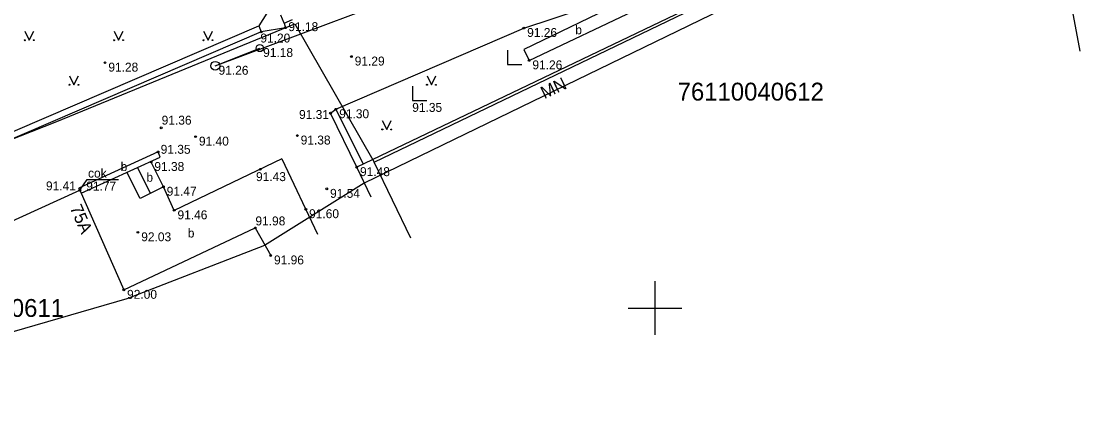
# Model space of a CAD drawing. Extents: x 634272 to 634544, y 247463 to 247653.
# Drawn here: x 634414.5 to 634473.8, y 247493.7 to 247516.1 of the extents above; entities that cross this region are included whole.
import ezdxf

# ---------------------------------------------------------------- set-up
doc = ezdxf.new("R2010")
doc.units = 0
for name, color, linetype in [('BUVE_BDET_####_####_#', 7, 'Continuous'), ('BUVE_BDET_####_TKST_#', 7, 'Continuous'), ('BUVE_COKL_####_####_#', 7, 'Continuous'), ('BUVE_EKAS_####_####_#', 7, 'Continuous'), ('BUVE_EKAS_ADRS_TKST_#', 7, 'Continuous'), ('BUVE_EKAS_RAKS_TKST_#', 7, 'Continuous'), ('CELI_CMAL_####_####_#', 7, 'Continuous'), ('CELI_SEGL_####_####_#', 7, 'Continuous'), ('ELEK_ELEM_####_####_#', 7, 'Continuous'), ('ELEK_STUT_####_####_#', 7, 'Continuous'), ('ELEK_VADV_ZSPR_####_#', 7, 'Continuous'), ('GEOD_ELEM_####_####_#', 7, 'Continuous'), ('NORB_ELEM_####_####_#', 7, 'Continuous'), ('NORB_ZOGS_KONT_####_#', 7, 'Continuous'), ('RAMI_UZMR_####_####_#', 7, 'Continuous'), ('RELJ_AATZ_####_TKST_#', 7, 'Continuous'), ('RELJ_ELEM_####_####_#', 7, 'Continuous'), ('ROBZ_KADS_####_TKST_#', 7, 'Continuous'), ('ROBZ_UZMR_####_####_#', 7, 'Continuous'), ('TERT_ELEM_####_####_#', 7, 'Continuous')]:
    doc.layers.add(name, color=color, linetype=linetype)

msp = doc.modelspace()

# ---------------------------------------------------------------- linework, layer by layer
at = {"layer": 'BUVE_BDET_####_####_#'}
msp.add_line((634429.124, 247508.347), (634431.133, 247504.145), dxfattribs=at)
for points in [[(634442.961, 247513.867), (634449.175, 247516.814), (634448.89, 247517.508), (634442.673, 247514.485), (634442.961, 247513.867)], [(634417.904, 247506.438), (634422.315, 247508.451), (634422.21, 247508.742), (634417.782, 247506.718)], [(634429.124, 247508.347), (634423.107, 247505.471)], [(634421.784, 247506.427), (634421.06, 247507.878)], [(634423.107, 247505.471), (634422.505, 247506.79), (634421.813, 247508.177)], [(634421.197, 247506.132), (634420.462, 247507.605)], [(634417.83, 247506.605), (634417.782, 247506.718)], [(634422.505, 247506.79), (634421.197, 247506.132)]]:
    msp.add_lwpolyline(points, dxfattribs=at)
at = {"layer": 'BUVE_COKL_####_####_#'}
msp.add_lwpolyline([(634417.83, 247506.605), (634418.235, 247507.205), (634419.988, 247507.205)], dxfattribs=at)
at = {"layer": 'BUVE_EKAS_####_####_#'}
msp.add_line((634434.121, 247506.21), (634433.316, 247507.888), dxfattribs=at)
for points in [[(634455.924, 247518.731), (634433.316, 247507.888)], [(634408.055, 247496.543), (634405.917, 247501.17), (634417.83, 247506.605), (634420.287, 247501.019)], [(634420.287, 247501.019), (634427.646, 247504.487), (634428.506, 247502.946)]]:
    msp.add_lwpolyline(points, dxfattribs=at)
at = {"layer": 'CELI_CMAL_####_####_#'}
for points in [[(634432.152, 247511.13), (634442.666, 247515.679), (634452.74, 247519.016), (634457.288, 247519.823)], [(634428.732, 247517.22), (634427.84, 247515.805)]]:
    msp.add_lwpolyline(points, dxfattribs=at)
at = {"layer": 'CELI_SEGL_####_####_#'}
msp.add_lwpolyline([(634429.265, 247515.95), (634429.333, 247515.697), (634427.981, 247515.463)], dxfattribs=at)
at = {"layer": 'ELEK_ELEM_####_####_#'}
for centre, radius in [((634427.898, 247514.558), 0.2), ((634425.403, 247513.565), 0.25)]:
    msp.add_circle(centre, radius, dxfattribs=at)
at = {"layer": 'ELEK_STUT_####_####_#'}
msp.add_lwpolyline([(634425.403, 247513.565), (634427.898, 247514.558)], dxfattribs=at)
at = {"layer": 'ELEK_VADV_ZSPR_####_#'}
msp.add_lwpolyline([(634425.403, 247513.565), (634452.967, 247523.892)], dxfattribs=at)
at = {"layer": 'GEOD_ELEM_####_####_#'}
for p, q in [((634450, 247501.5), (634450, 247500)), ((634448.5, 247500), (634450, 247500)), ((634450, 247500), (634450, 247498.5)), ((634450, 247500), (634451.5, 247500))]:
    msp.add_line(p, q, dxfattribs=at)
at = {"layer": 'NORB_ELEM_####_####_#'}
for q in [(634429.066, 247516.408), (634429.724, 247516.149)]:
    msp.add_line((634429.265, 247515.95), q, dxfattribs=at)
at = {"layer": 'NORB_ZOGS_KONT_####_#'}
for points in [[(634427.84, 247515.805), (634427.981, 247515.463), (634397.16, 247502.201), (634397.008, 247502.541), (634427.84, 247515.805)], [(634433.316, 247507.888), (634431.85, 247510.916), (634432.152, 247511.13), (634433.676, 247508.061)]]:
    msp.add_lwpolyline(points, dxfattribs=at)
at = {"layer": 'RAMI_UZMR_####_####_#'}
msp.add_lwpolyline([(634466.614, 247558.36), (634469.076, 247546.545), (634471.781, 247533.982), (634471.429, 247521.859), (634457.577, 247518.735), (634456.257, 247517.942), (634433.742, 247506.986), (634428.158, 247503.509), (634420.457, 247500.517), (634407.71, 247496.821), (634397.043, 247493.687), (634395.968, 247498.053), (634390.559, 247517.942), (634387.41, 247527.318), (634427.834, 247538.059), (634425.364, 247546.393), (634376.048, 247532.596), (634371.988, 247530.992)], dxfattribs=at)
at = {"layer": 'RELJ_ELEM_####_####_#'}
for centre in [(634427.981, 247515.463), (634429.333, 247515.697), (634442.666, 247515.679), (634419.239, 247513.74), (634433.021, 247514.081), (634442.961, 247513.867), (634431.85, 247510.916), (634432.152, 247511.13), (634422.383, 247510.091), (634424.306, 247509.599), (634429.998, 247509.658), (634422.21, 247508.742), (634421.813, 247508.177), (634427.925, 247507.774), (634433.316, 247507.888), (634417.83, 247506.605), (634422.505, 247506.79), (634431.642, 247506.674), (634423.107, 247505.471), (634430.469, 247505.534), (634421.079, 247504.241), (634427.646, 247504.487), (634428.506, 247502.946), (634420.287, 247501.019)]:
    msp.add_circle(centre, 0.05, dxfattribs=at)
at = {"layer": 'ROBZ_UZMR_####_####_#'}
for points in [[(634472.285, 247522.369), (634473.767, 247514.38)], [(634434.292, 247508.17), (634458.415, 247519.805)], [(634416.541, 247510.45), (634429.865, 247515.906)], [(634429.865, 247515.906), (634434.292, 247508.17)], [(634397.146, 247502.796), (634416.541, 247510.45)], [(634436.354, 247503.92), (634434.292, 247508.17)]]:
    msp.add_lwpolyline(points, dxfattribs=at)
at = {"layer": 'TERT_ELEM_####_####_#'}
for p, q in [((634414.75, 247515.5), (634415, 247515)), ((634415, 247515), (634415.25, 247515.5)), ((634419.75, 247515.5), (634420, 247515)), ((634420, 247515), (634420.25, 247515.5)), ((634424.75, 247515.5), (634425, 247515)), ((634425, 247515), (634425.25, 247515.5)), ((634441.753, 247514.437), (634441.753, 247513.637)), ((634441.753, 247513.637), (634442.553, 247513.637)), ((634417.25, 247513), (634417.5, 247512.5)), ((634417.5, 247512.5), (634417.75, 247513)), ((634437.25, 247513), (634437.5, 247512.5)), ((634437.5, 247512.5), (634437.75, 247513)), ((634436.436, 247512.417), (634436.436, 247511.617)), ((634436.436, 247511.617), (634437.236, 247511.617)), ((634434.75, 247510.5), (634435, 247510)), ((634435, 247510), (634435.25, 247510.5))]:
    msp.add_line(p, q, dxfattribs=at)
for centre, radius in [((634414.75, 247515), 0.028), ((634415.25, 247515), 0.0263), ((634419.75, 247515), 0.028), ((634420.25, 247515), 0.0263), ((634424.75, 247515), 0.028), ((634425.25, 247515), 0.0263), ((634417.25, 247512.5), 0.028), ((634417.75, 247512.5), 0.0263), ((634437.25, 247512.5), 0.028), ((634437.75, 247512.5), 0.0263), ((634434.75, 247510), 0.028), ((634435.25, 247510), 0.0263)]:
    msp.add_circle(centre, radius, dxfattribs=at)

# ---------------------------------------------------------------- texts
at = {"layer": 'BUVE_BDET_####_TKST_#'}
for p in [(634445.545, 247515.33), (634420.115, 247507.673), (634421.554, 247507.074), (634423.868, 247503.952)]:
    msp.add_text('b', height=0.5, dxfattribs=at).set_placement(p)
at = {"layer": 'BUVE_COKL_####_####_#'}
for s, p in [('cok', (634418.29, 247507.307)), (' 91.77', (634418, 247506.582))]:
    msp.add_text(s, height=0.5, dxfattribs=at).set_placement(p)
at = {"layer": 'BUVE_EKAS_ADRS_TKST_#'}
msp.add_text('75A', height=0.7, rotation=293.74228, dxfattribs=at).set_placement((634417.254, 247505.612))
at = {"layer": 'BUVE_EKAS_RAKS_TKST_#'}
msp.add_text('MN', height=0.7, rotation=25.62279, dxfattribs=at).set_placement((634443.819, 247511.691))
at = {"layer": 'RELJ_AATZ_####_TKST_#'}
for s, p in [(' 91.18', (634429.308, 247515.506)), (' 91.20', (634427.743, 247514.869)), (' 91.26', (634442.666, 247515.179)), (' 91.18', (634427.898, 247514.058)), (' 91.28', (634419.239, 247513.24)), (' 91.29', (634433.021, 247513.581)), (' 91.26', (634442.961, 247513.367)), (' 91.26', (634425.403, 247513.065)), (' 91.35', (634436.237, 247510.985)), (' 91.36', (634422.221, 247510.271)), (' 91.31', (634429.908, 247510.589)), (' 91.30', (634432.152, 247510.63)), (' 91.40', (634424.306, 247509.099)), (' 91.38', (634429.998, 247509.158)), (' 91.35', (634422.166, 247508.639)), (' 91.38', (634421.813, 247507.677)), (' 91.48', (634433.316, 247507.388)), (' 91.41', (634415.75, 247506.593)), (' 91.43', (634427.499, 247507.109)), (' 91.47', (634422.505, 247506.29)), (' 91.54', (634431.642, 247506.174)), (' 91.46', (634423.107, 247504.971)), (' 91.60', (634430.469, 247505.034)), (' 91.98', (634427.467, 247504.63)), (' 92.03', (634421.079, 247503.741)), (' 91.96', (634428.506, 247502.446)), (' 92.00', (634420.287, 247500.519))]:
    msp.add_text(s, height=0.5, dxfattribs=at).set_placement(p)
at = {"layer": 'ROBZ_KADS_####_TKST_#'}
for s, p in [('76110040612', (634451.27, 247511.619)), ('76110040611', (634408.763, 247499.507))]:
    msp.add_text(s, height=1, dxfattribs=at).set_placement(p)

doc.saveas('drawing.dxf')
